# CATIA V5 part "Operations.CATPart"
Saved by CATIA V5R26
Part number: Operations
Bounding box of the stored display mesh (mm): x 771.903 to 1396.157, y -802.795 to -660.109, z 0 to 524.096
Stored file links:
  D:\LinkedIn Learning\NURBS\CATIA\Class Parts\Operations.CATPart
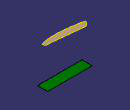
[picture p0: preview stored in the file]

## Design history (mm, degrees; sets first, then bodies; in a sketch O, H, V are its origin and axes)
AxisSystem1: origin (0, 0, 0), X (1, 0, 0), Y (0, 1, 0), Z (0, 0, 1)
Set1
  CLDGeom1 "Mesh"
  DatumSurface1
Body1 (main body)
